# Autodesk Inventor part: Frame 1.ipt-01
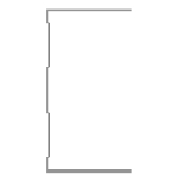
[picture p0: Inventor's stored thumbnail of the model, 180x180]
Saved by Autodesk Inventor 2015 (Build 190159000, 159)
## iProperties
_CCFamilyMember: 1
_CCFamilyDisplayName: Kévin - Kévin Novo
_FrameMemberDoc: Frame Member File
_Version: 15.0.0
_GetPNFromCC: 1
Created: 2015-04
Part Number: Frame 1.ipt-01
Material: Aluminum 6061
Description: Kévin Novo
Document SubType Name: Modeling
Standard: Kevin
Designer: suporte
Standards Organization: Kevin
Language: en-US
Size Designation: (Unnamed 1)
Categories: <MemberInstance><Categories><Category DisplayName="Structural Shapes" InternalName="089c4875-fa83-4c05-b084-43b9cc11f5ed" Mnemonic="GRDR"><CategoryParameter Dis
Density: 2.7 g/cm^3
Appearance: Aluminum - Flat
IsCustomPart: 1
G_L: 1150,000 mm
G_W: 50,000 mm
G_H: 75,000 mm
+E893309B-5B4C-4D46-95ED-955E91FBA60A+CUTDETAIL1: Cut
+6052804E-6593-4938-B763-12C79B00D91D+CUTDETAIL2: Cut
Author: suporte
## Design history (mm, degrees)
node "Start Plane"
node "End Plane"
sketch "Sketch"
  geometry: L1 (24.7, 37.5)-(24.7, 36.9); L2 (24.7, 36.9)-(-24.7, 36.9); L3 (-24.7, -36.9)-(24.7, -36.9); L4 (24.7, -36.9)-(24.7, -37.5); L5 (24.7, -37.5)-(-25.3, -37.5); L6 (-25.3, 37.5)-(24.7, 37.5); L7 (-24.7, 36.9)-(-24.7, 31.9); L8 (-24.7, 31.9)-(-23.3, 30.5); L9 (-23.3, 30.5)-(-23.3, 10.934); L10 (-23.3, 10.934)-(-24.7, 9.534); L11 (-24.7, 9.534)-(-24.7, -9.534); L12 (-24.7, -9.534)-(-23.3, -10.934); L13 (-23.3, -10.934)-(-23.3, -30.5); L14 (-23.3, -30.5)-(-24.7, -31.9); L15 (-24.7, -31.9)-(-24.7, -36.9); L16 (-25.3, -37.5)-(-25.3, -31.651); L17 (-25.3, -31.651)-(-23.9, -30.251); L18 (-23.9, -30.251)-(-23.9, -11.183); L19 (-23.9, -11.183)-(-25.3, -9.783); L20 (-25.3, -9.783)-(-25.3, 9.783); L21 (-25.3, 9.783)-(-23.9, 11.183); L22 (-23.9, 11.183)-(-23.9, 30.251); L23 (-23.9, 30.251)-(-25.3, 31.651); L24 (-25.3, 31.651)-(-25.3, 37.5); L25 (-25.3, 0)-(30.37, 0); 3 further points
  constraints: 50 end point, 10 point on line, 9 parallel, 5 perpendicular, 4 equal length, 3 midpoint, 3 vertical, 2 vertical alignment, 1 collinear, 1 horizontal, 1 horizontal alignment
  dimensions: "d3" = 0.6 distance of L1.start L1.end (= d6); "d5" = 75 distance between parallel lines of L5 L6; "d6" = 0.6 distance between parallel lines of L24 L7 (= d8); "d7" = 0.6 distance between parallel lines of L8 L23 (= d8); "d8" = 0.6 distance between parallel lines of L22 L9 (= d12); "Espessura" = 0.6 distance between parallel lines of L17 L14; "d10" = 0.6 distance between parallel lines of L13 L18 (= Espessura); "d11" = 0.6 distance between parallel lines of L12 L19 (= Espessura); "d12" = 0.6 distance between parallel lines of L21 L10 (= d11); "d13" = 5 distance of L2.end L7.end; "d15" = 135 deg angle of L9 L8; "d16" = 2 distance between parallel lines of L24 L9; "d17" = 50 distance of L6.start L1.start
extrude "Body" join sketch "Sketch" stored distance "d24" = 0.13; taper "d25" = 0 deg
node "Driven Length"
  sketch "Sketch10"
    geometry: L1 (0, 0)-(10, 0) reference
    constraints: 2 end point, 1 horizontal
  workplane "Work Plane7"
  sketch "Sketch11"
    geometry: L1 (-2, 12.5)-(12, 12.5) reference; L2 (-2, 1162.5)-(12, 1162.5) reference
    dimensions: "d27" = 1150 distance between parallel lines of L1 L2 (derived)
workplane "Work Plane8"
split "Split1"
workplane "Work Plane9"
split "Split2"
body "Solid1"
other parameters: "G_OFFSET_START" = -12.5 [user parameter; used in 1 equation term], "G_OFFSET_END" = -37.5 [user parameter; used in 1 equation term], "d22" = 12.5 (= -G_OFFSET_START), "d23" = 1162.5 (= tamanho + G_OFFSET_END), "G_L" = 1150 (= d27) [user parameter], "d34" = 90 deg
